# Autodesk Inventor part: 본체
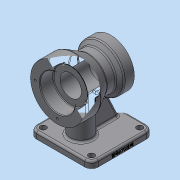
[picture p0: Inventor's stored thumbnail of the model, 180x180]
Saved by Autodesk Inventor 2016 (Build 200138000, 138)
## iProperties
Created: 2019-01
Part Number: 본체
Material: 일반
Document SubType Name: Modeling
Designer: Administrator
Density: 1 g/cm^3
Appearance: 기본값
Author: Administrator
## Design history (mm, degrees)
sketch "스케치1"
  geometry: L1 (0, 40)-(25, 40); L2 (25, 40)-(45.785, 28); L3 (45.785, 28)-(59.126, 28); L4 (59.126, 28)-(65, 35); L5 (65, 35)-(80, 35); L6 (-53.077, 0)-(89.279, 0); L7 (0, 40)-(0, 0); L8 (80, 35)-(80, 0)
  constraints: 16 end point, 2 horizontal, 2 parallel, 2 perpendicular, 2 point on line, 1 vertical alignment
  dimensions: "d0" = 80 diameter of L1 L6; "d1" = 70 diameter of L5 L6; "d2" = 25 distance of L1.start L1.end; "d3" = 15 distance of L4.end L5.end; "d4" = 56 diameter of L3 L6; "d5" = 30 deg angle of L3 L2; "d6" = 50 deg angle of L3 L4; "d7" = 80 horizontal distance of L5.end L1.start
revolve "회전1" sketch "스케치1" stored, may be unused: angle "d8" = 90 deg
sketch "스케치2"
  geometry: L1 (0, 26)-(20, 26); L2 (20, 26)-(20, 16); L3 (20, 16)-(63, 16); L4 (63, 16)-(63, 20); L5 (63, 20)-(80, 20); L6 (80, -35)-(80, 35) reference; L7 (-21.314, 0)-(113.108, 0); L8 (0, -40)-(0, 40) reference; L9 (0, 26)-(0, 0); L10 (80, 20)-(80, 0)
  constraints: 16 end point, 4 point on line, 2 perpendicular, 1 collinear, 1 horizontal, 1 midpoint
  dimensions: "d9" = 20 distance of L1.start L1.end; "d10" = 17 distance of L4.end L5.end; "d11" = 52 diameter of L1 L7; "d12" = 32 diameter of L3 L7; "d13" = 40 diameter of L5 L7
revolve "회전2" sketch "스케치2" stored, may be unused: angle "d14" = 90 deg
node "작업 평면1"
sketch "스케치3"
  geometry: L1 (40, 0)-(-40, 0) reference; L2 (-46, 5)-(46, 5); L3 (46, 5)-(46, 97); L4 (46, 97)-(-46, 97); L5 (-46, 97)-(-46, 5); L6 (-46, 5)-(46, 97); L7 (46, 5)-(-46, 97); 4 further points
  constraints: 12 end point, 4 midpoint, 2 parallel, 1 horizontal, 1 perpendicular, 1 vertical alignment
  dimensions: "d16" = 92 distance of L4.end L3.end; "d17" = 92 distance of L3.end L2.end; "d18" = 5 distance between parallel lines of L1 L2
extrude "돌출1" join sketch "스케치3" distance "d19" = 10; taper "d20" = 0 deg
sketch "스케치4"
  geometry: L1 (-46, 97)-(-46, 5) reference; L2 (-46, 5)-(46, 5) reference; C1 r 16 at (0, 35); 1 further point
  constraints: 1 centre point, 1 vertical alignment
  dimensions: "d21" = 16 radius of C1; "d22" = 46 distance from line of L1 C1.centre (derived); "d23" = 30 distance from line of L2 C1.centre
extrude "돌출2" join sketch "스케치4" stored distance "d24" = 10; taper "d25" = 0 deg
sketch "스케치5"
  geometry: L1 (97, -70)-(5, -70) reference; L2 (87, -70)-(70.679, -35); L3 (65, -35)-(80, -35) reference; L4 (97, -80)-(97, -70) reference; 1 further point
  constraints: 2 end point, 2 point on line
  dimensions: "d26" = 10 distance from line of L4 L2.start; "d27" = 25 deg angle of L4 L2
feature "리브1" sketch "스케치5" dims "d28" = 1, "d29" = 10, "d30" = 0, "d31" = 0, "d32" = 1, "d33" = 1
sketch "스케치6"
  geometry: L1 (0, 0)-(0, 33); C1 r 16 at (0, 0) reference; 2 further points
  constraints: 2 end point, 1 coincident, 1 vertical
  dimensions: "d34" = 33 distance of L1.start L1.end
hole "구멍1" sketch "스케치6" at (0, 33) diameter "d35" = 3.242; stored, may be unused: countersink angle "d39" = 90 deg, drill point angle "d41" = 118 deg; dims "d36" = 9, "d37" = 4, "d38" = 2, "d40" = 11
sketch "스케치7"
  geometry: L1 (0, 0)-(0, -27.5); C1 r 16 at (0, 0) reference; 2 further points
  constraints: 2 end point, 1 coincident, 1 vertical
  dimensions: "d45" = 27.5 distance of L1.start L1.end
hole "구멍2" sketch "스케치7" at (0, -27.5) diameter "d46" = 3.242; stored, may be unused: countersink angle "d50" = 90 deg, drill point angle "d52" = 118 deg; dims "d47" = 9, "d48" = 4, "d49" = 2, "d51" = 11
sketch "스케치8"
  geometry: L1 (0, 0)-(-10, 0) reference; L2 (0, 0)-(0, 92) reference; 2 further points
  constraints: 1 other
  dimensions: "d56" = 46 distance from line of L1 point (-4, 46); "d57" = 4 distance from line of L2 point (-4, 46)
feature "엠보싱1" sketch "스케치8" dims "d0" = 80, "d1" = 70, "d2" = 25, "d3" = 15, "d4" = 56, "d5" = 30 deg, "d6" = 50 deg, "d7" = 80, "d9" = 20, "d10" = 17, "d11" = 52, "d12" = 32, "d13" = 40, "d58" = 0.5, "d59" = 0
sketch "스케치9"
  geometry: L1 (-46, 97)-(-46, 5) reference; L2 (46, 97)-(-46, 97) reference; 2 further points
  dimensions: "d60" = 10 distance from line of L1 point (-36, 87); "d61" = 10 distance from line of point (-36, 87) L2
hole "구멍3" sketch "스케치9" at (-36, 87) diameter "d62" = 9; stored, may be unused: countersink angle "d66" = 90 deg, drill point angle "d68" = 118 deg; dims "d63" = 9, "d64" = 4, "d65" = 2, "d67" = 11
fillet "모깎기1" dims "d75" = 0.6, "d76" = 1, "d77" = 10
chamfer "모따기1" distance "d78" = 1; stored, may be unused: second distance "d79" = 2, angle "d80" = 45 deg
fillet "모깎기2" dims "d81" = 3
feature "분할1"
node "솔리드1"
pattern_circular "원형 패턴1" dims angle "d43" = 360 deg
pattern_circular "원형 패턴2" dims angle "d54" = 360 deg
pattern_linear "직사각형 패턴1" dims "d71" = 72, "d74" = 72
